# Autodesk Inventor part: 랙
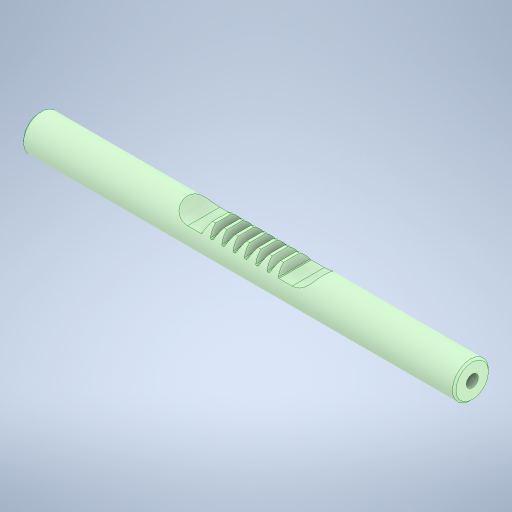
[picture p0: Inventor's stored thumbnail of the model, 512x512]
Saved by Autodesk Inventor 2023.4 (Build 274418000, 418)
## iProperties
Created: 2024-05
Part Number: 랙
Material: 강철, 탄소
Document SubType Name: Modeling
Designer: EDU-001
Density: 7.85 g/cm^3
Appearance: 기본값
Author: jhkim
Sending System: Autodesk Inventor 2025
Preprocessor: ST-DEVELOPER v20
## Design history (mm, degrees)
node "랙1"
node "솔리드2"
node "솔리드1"
